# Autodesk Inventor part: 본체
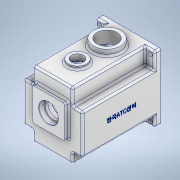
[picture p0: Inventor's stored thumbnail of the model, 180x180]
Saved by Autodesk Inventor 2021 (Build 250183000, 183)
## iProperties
Created: 2022-08
Part Number: 본체
Material: 알루미늄 6061
Document SubType Name: Modeling
Designer: Owner
Mass: 1403.62 g
Surface Area: 1171.87 cm^2
Volume: 519.86 cm^3
Density: 2.7 g/cm^3
Appearance: 알루미늄 - 평지
Author: Owner
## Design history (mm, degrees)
sketch "스케치1"
  geometry: L1 (-49, 55)-(49, 55); L2 (49, 55)-(49, -55); L3 (49, -55)-(-49, -55); L4 (-49, -55)-(-49, 55); L5 (-49, 55)-(49, -55); L6 (49, 55)-(-49, -55); 1 further point
  constraints: 12 end point, 2 midpoint, 2 parallel, 1 horizontal, 1 perpendicular
  dimensions: "d0" = 98 distance of L2.end L3.end; "d1" = 110 distance of L1.end L2.end
extrude "돌출1" new body sketch "스케치1" stored distance "d2" = 130; taper "d3" = 0 deg
sketch "스케치2"
  geometry: L1 (-27, 33)-(27, 33); L2 (27, 33)-(27, -21); L3 (27, -21)-(-27, -21); L4 (-27, -21)-(-27, 33); L5 (-27, 33)-(27, -21); L6 (27, 33)-(-27, -21); L7 (49, -55)-(49, 55) reference; L8 (-49, -55)-(49, -55) reference; 4 further points
  constraints: 12 end point, 4 midpoint, 2 parallel, 1 horizontal, 1 perpendicular, 1 vertical alignment
  dimensions: "d4" = 54 distance of L2.end L3.end; "d5" = 54 distance of L1.end L2.end; "d131" = 61 vertical distance of point (0, -55) point (27, 6)
extrude "돌출2" join sketch "스케치2" distance "d6" = 7; taper "d7" = 0 deg
sketch "스케치3"
  geometry: L1 (49, 55)-(-49, 55) reference; L2 (-49, 55)-(-33, 55); L3 (-33, 55)-(-33, 28); L4 (-33, 28)-(-49, 28); L5 (-49, 28)-(-49, 55); L6 (49, 55)-(33, 55); L7 (33, 55)-(33, 28); L8 (33, 28)-(49, 28); L9 (49, 28)-(49, 55); L10 (-49, 55)-(-49, -55) reference; L11 (-49, -55)-(-33, -55); L12 (-33, -55)-(-33, -38); L13 (-33, -38)-(-49, -38); L14 (-49, -38)-(-49, -55); L15 (49, -55)-(49, 55) reference; L16 (49, -55)-(33, -55); L17 (33, -55)-(33, -38); L18 (33, -38)-(49, -38); L19 (49, -38)-(49, -55); 5 further points
  constraints: 32 end point, 8 parallel, 4 horizontal, 4 perpendicular, 2 point on line
  dimensions: "d8" = 16 distance between parallel lines of L5 L3; "d9" = 16 distance between parallel lines of L9 L7; "d10" = 27 distance between parallel lines of L4 L1; "d11" = 17 distance between parallel lines of L11 L13; "d12" = 16 distance between parallel lines of L10 L12; "d13" = 16 distance between parallel lines of L15 L17
extrude "돌출3" cut sketch "스케치3" distance "d14" = 120; taper "d15" = 0 deg
sketch "스케치4"
  geometry: L1 (0, 0)-(98, 0) reference; C1 r 15 at (49, -89); 1 further point
  constraints: 1 centre point, 1 vertical alignment
  dimensions: "d16" = 30 diameter of C1; "d17" = 89 distance from line of L1 C1.centre
extrude "돌출4" join sketch "스케치4" distance "d18" = 5; taper "d19" = 0 deg
sketch "스케치5"
  geometry: L1 (0, 0)-(98, 0) reference; C1 r 22.5 at (49, -40); 1 further point
  constraints: 1 centre point, 1 vertical alignment
  dimensions: "d20" = 45 diameter of C1; "d21" = 40 distance from line of L1 C1.centre
extrude "돌출5" join sketch "스케치5" distance "d22" = 10; taper "d23" = 0 deg
sketch "스케치6"
  geometry: L1 (-26, 48)-(26, 48); L2 (26, 48)-(26, 20.088); L3 (26, 20.088)-(-26, 20.088); L4 (-26, 20.088)-(-26, 48); L5 (49, 55)-(-49, 55) reference; L6 (-49, -55)-(49, -55) reference; C1 r 45 at (0, -5); 4 further points
  constraints: 8 end point, 2 parallel, 2 vertical alignment, 1 centre point, 1 horizontal, 1 midpoint, 1 perpendicular
  dimensions: "d25" = 52 distance of L2.end L3.end; "d26" = 7 distance between parallel lines of L5 L1; "d27" = 50 distance from line of L6 C1.centre; "d28" = 90 diameter of C1
extrude "돌출6" cut sketch "스케치6" distance "d29" = 9; taper "d30" = 0 deg
sketch "스케치7"
  geometry: L1 (-23, 45)-(23, 45); L2 (23, 45)-(23, 8.693); L3 (23, 8.693)-(-23, 8.693); L4 (-23, 8.693)-(-23, 45); L5 (49, 55)-(-49, 55) reference; C1 r 42 at (0, -5); A1 r 45 centre (0, -5) between (-26, 31.729) and (26, 31.729) reference; 4 further points
  constraints: 8 end point, 2 parallel, 1 centre point, 1 concentric, 1 horizontal, 1 midpoint, 1 perpendicular, 1 vertical alignment
  dimensions: "d31" = 10 distance between parallel lines of L5 L1; "d32" = 46 distance between parallel lines of L4 L2; "d33" = 84 diameter of C1
extrude "돌출7" cut sketch "스케치7" distance "d34" = 112; taper "d35" = 0 deg
sketch "스케치11"
  geometry: A1 r 15 centre (0, -25) between (-8.978, -12.984) and (8.978, -12.984); A2 r 21 centre (0, 6) between (8.978, -12.984) and (-8.978, -12.984); A3 r 42 centre (0, -5) between (-23, 30.143) and (23, 30.143) reference; 1 further point
  constraints: 4 point on circle, 2 centre point, 2 vertical alignment
  dimensions: "d47" = 30 diameter of A1; "d49" = 42 diameter of A2; "d126" = 11 distance of A2.centre A3.centre; "d127" = 20 distance of A1.centre A3.centre
extrude "돌출11" join sketch "스케치11" distance "d51" = 7; taper "d52" = 0 deg
sketch "스케치12"
  geometry: C1 r 17.5 at (0, 6); A1 r 21 centre (0, 6) between (8.978, -12.984) and (-8.978, -12.984) reference; 1 further point
  constraints: 1 centre point, 1 concentric
  dimensions: "d53" = 35 diameter of C1
extrude "돌출12" cut sketch "스케치12" distance "d54" = 10; taper "d55" = 0 deg
sketch "스케치14"
  geometry: C1 r 11 at (0, -25); A1 r 15 centre (0, -25) between (-8.978, -12.984) and (8.978, -12.984) reference; 1 further point
  constraints: 1 centre point, 1 concentric
  dimensions: "d59" = 22 diameter of C1
extrude "돌출14" cut sketch "스케치14" distance "d60" = 7; taper "d61" = 0 deg
sketch "스케치15"
  geometry: C1 r 9.5 at (0, 0); C2 r 11 at (0, 0) reference; 1 further point
  constraints: 1 centre point, 1 concentric
  dimensions: "d62" = 19 diameter of C1
extrude "돌출15" cut sketch "스케치15" distance "d63" = 3; taper "d64" = 0 deg
sketch "스케치16"
  geometry: L1 (-35.778, -1.006)-(-41.81, -1.006); L2 (-41.809, -9)-(-35.778, -9); L3 (-35.778, -9)-(-35.778, -8.994); L4 (36.222, -1.006)-(41.81, -1.006); L5 (41.809, -9)-(36.222, -9); L6 (36.222, -9)-(36.222, -8.994); A1 r 36 centre (0, -5) between (35.778, -1.006) and (35.778, -8.994); A2 r 42 centre (0, -5) between (-23, 30.143) and (23, 30.143) reference; A3 r 4 centre (-36, -5) between (-36, -9) and (-36.222, -1.006); A4 r 4 centre (36, -5) between (36.222, -1.006) and (36.222, -8.994); 1 further point
  constraints: 17 point on circle, 12 end point, 3 centre point, 3 point on line, 2 horizontal, 2 horizontal alignment, 2 parallel, 2 tangent, 1 concentric
  dimensions: "d65" = 72 diameter of A1; "d66" = 8 diameter of A4; "d67" = 8 diameter of A3
extrude "돌출16" join sketch "스케치16" stored distance "d68" = 8 (= d66); taper "d69" = 0 deg
sketch "스케치17"
  geometry: C1 r 10 at (0, 0); 1 further point
  constraints: 1 centre point
  dimensions: "d70" = 20 diameter of C1
sketch "스케치18"
  geometry: C1 r 15 at (23, 80) reference; C2 r 15 at (23, 80); 1 further point
  constraints: 1 centre point, 1 coincident
  dimensions: "d71" = 30 diameter of C2
extrude "돌출17" cut sketch "스케치18" distance "d72" = 5; taper "d73" = 0 deg
extrude "돌출18" cut sketch "스케치17" stored distance "d74" = 5; taper "d75" = 0 deg
sketch "스케치19"
  geometry: C1 r 22.5 at (0, 0) reference; 2 further points
  constraints: 1 coincident
hole "구멍1" sketch "스케치19" at (0, 0) diameter "d76" = 33.376; stored, may be unused: countersink angle "d80" = 90 deg, drill point angle "d82" = 118 deg; dims "d77" = 70, "d78" = 4, "d79" = 2, "d81" = 77.3
chamfer "모따기1" distance "d83" = 1; stored, may be unused: second distance "d84" = 2, angle "d85" = 45 deg
fillet "모깎기1" dims "d86" = 3
fillet "모깎기2" dims "d87" = 3
sketch "스케치20"
  geometry: L1 (-130, 104)-(-130, 83) reference; L2 (-7, 107)-(-127, 107) reference; 3 further points
  constraints: 1 other
  dimensions: "d90" = 65 distance from line of L1 point (-65, 47); "d91" = 60 distance from line of L2 point (-65, 47)
feature "엠보싱1" sketch "스케치20" dims "d92" = 0.5, "d93" = 0
sketch "스케치21"
  geometry: L1 (-30, 55)-(-46, 55) reference; L2 (-49, 52)-(-49, 25) reference; L3 (-46, 55)-(46, 55) reference; L4 (49, 25)-(49, 52) reference; L5 (49, 52)-(49, -52) reference; L6 (30, -55)-(46, -55) reference; L7 (-49, -52)-(-49, 52) reference; L8 (46, -55)-(-46, -55) reference; C1 r 3.5 at (-42, 48); C2 r 3.5 at (42, 48); C3 r 3.5 at (42, -48); C4 r 3.5 at (-42, -48); 1 further point
  constraints: 4 centre point
  dimensions: "d94" = 7 diameter of C4; "d95" = 7 diameter of C1; "d96" = 7 diameter of C2; "d97" = 7 diameter of C3; "d98" = 7 distance from line of C1.centre L1; "d99" = 7 distance from line of L2 C1.centre; "d100" = 7 distance from line of L3 C2.centre; "d101" = 7 distance from line of L4 C2.centre; "d102" = 7 distance from line of L5 C3.centre; "d103" = 7 distance from line of L6 C3.centre; "d104" = 7 distance from line of L7 C4.centre; "d105" = 7 distance from line of L8 C4.centre
extrude "돌출19" cut sketch "스케치21" stored distance "d106" = 7 (= d94); taper "d107" = 0 deg
fillet "모깎기5" dims "d108" = 6
fillet "모깎기6" dims "d109" = 3
fillet "모깎기7" dims "d110" = 3
fillet "모깎기8" dims "d111" = 3
fillet "모깎기9" dims "d112" = 3
sketch "스케치22"
  geometry: A1 r 4 centre (-36, -5) between (-36, -9) and (-35.778, -1.006) reference; A2 r 4 centre (36, -5) between (36.222, -1.006) and (36.222, -8.994) reference; 3 further points
  constraints: 2 coincident
hole "구멍2" sketch "스케치22" at (-36, -5), (36, -5) diameter "d113" = 3.242; stored, may be unused: countersink angle "d117" = 90 deg, drill point angle "d119" = 118 deg; dims "d114" = 7, "d115" = 4, "d116" = 2, "d118" = 9
fillet "모깎기10" dims "d120" = 3
fillet "모깎기11" dims "d121" = 6
fillet "모깎기12" dims "d122" = 0.3
sketch "스케치24"
  geometry: L1 (-30, -55)-(30, -55) reference; C1 r 16 at (0, 6); 1 further point
  constraints: 1 centre point, 1 vertical alignment
  dimensions: "d133" = 61 distance from line of L1 C1.centre; "d134" = 32 diameter of C1
extrude "돌출21" cut sketch "스케치24" distance "d135" = 8.3; taper "d136" = 0 deg
sketch "스케치25"
  geometry: L1 (-30, -61)-(30, -61) reference; C1 r 14 at (0, 0); 1 further point
  constraints: 1 centre point, 1 vertical alignment
  dimensions: "d137" = 61 distance from line of L1 C1.centre; "d138" = 28 diameter of C1
extrude "돌출22" cut sketch "스케치25" distance "d139" = 8.3; taper "d140" = 0 deg
chamfer "모따기3" distance "d141" = 0.8; stored, may be unused: second distance "d142" = 2, angle "d143" = 30 deg
fillet "모깎기13" dims "d144" = 3
fillet "모깎기14" dims "d145" = 0.3
chamfer "모따기4" distance "d147" = 1; stored, may be unused: second distance "d148" = 2, angle "d149" = 60 deg
node "솔리드1"
feature "A9D066F2-1C7D-4E18-AEED-F7BC21143FA4" dims "d113" = 3.242, "d114" = 7, "d115" = 4, "d116" = 2, "d117" = 90 deg, "d118" = 9, "d119" = 118 deg
